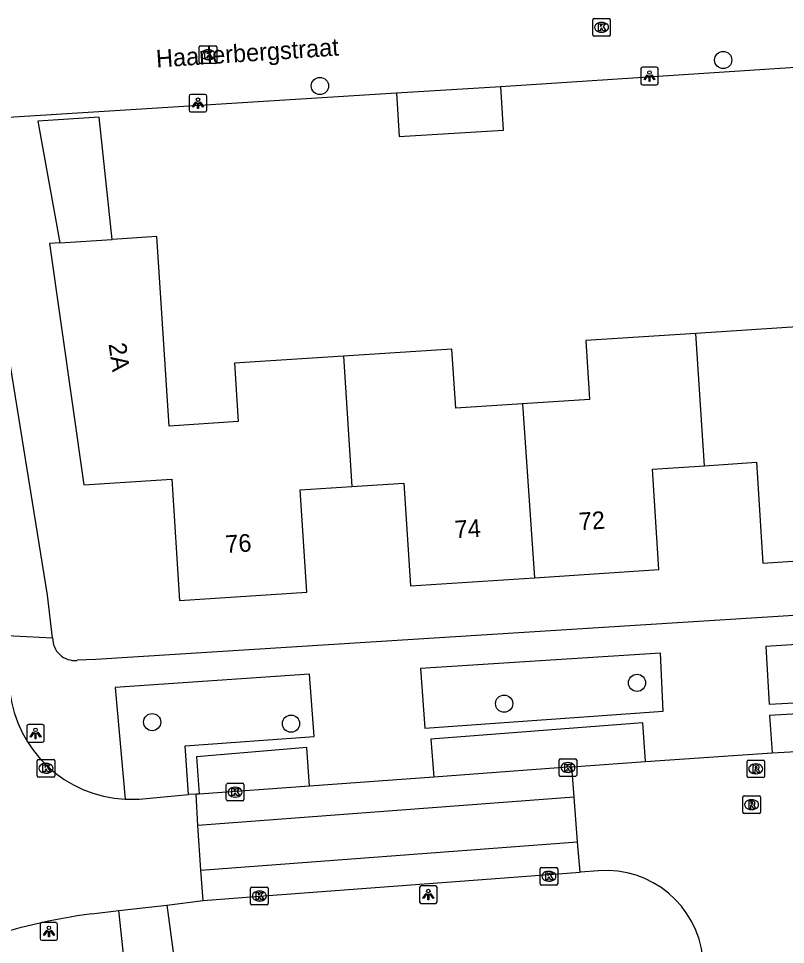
# Model space of a CAD drawing. Extents: x 159689 to 160786, y 387323 to 388339.
# Drawn here: x 160177 to 160220.6, y 388016 to 388068.6 of the extents above; entities that cross this region are included whole.
import ezdxf

# ---------------------------------------------------------------- set-up
doc = ezdxf.new("R2010")
doc.units = 0
for name, color, linetype in [('IMGEO_Boom', 7, 'Continuous'), ('IMGEO_Kolk', 7, 'Continuous'), ('IMGEO_Lichtpunt', 7, 'Continuous'), ('IMGEO_Openbare_ruimte_label', 7, 'Continuous'), ('IMGEO_Pand', 7, 'Continuous'), ('IMGEO_Pand_nummerreeks', 7, 'Continuous'), ('IMGEO_Rijbaan_lokaal_gesloten', 7, 'Continuous'), ('IMGEO_Rijbaan_lokaal_open', 7, 'Continuous'), ('IMGEO_Rioolput', 7, 'Continuous'), ('IMGEO_Voetpad_open', 7, 'Continuous')]:
    doc.layers.add(name, color=color, linetype=linetype)

msp = doc.modelspace()

# ---------------------------------------------------------------- linework, layer by layer
at = {"layer": 'IMGEO_Boom'}
for centre in [(160217.02, 388066.25), (160194.088, 388064.776), (160212.121, 388030.861), (160204.562, 388029.677), (160184.551, 388028.628), (160192.447, 388028.541)]:
    msp.add_circle(centre, 0.489, dxfattribs=at)
at = {"layer": 'IMGEO_Kolk'}
for p, q in [((160209.6, 388067.683), (160209.6, 388068.535)), ((160209.675, 388068.609), (160210.527, 388068.609)), ((160210.088, 388068.389), (160210.113, 388068.389)), ((160210.601, 388068.535), (160210.601, 388067.683)), ((160210.111, 388067.829), (160210.086, 388067.829)), ((160210.527, 388067.609), (160209.675, 388067.609)), ((160187.227, 388066.126), (160187.227, 388066.978)), ((160187.302, 388067.052), (160188.154, 388067.052)), ((160187.715, 388066.832), (160187.74, 388066.832)), ((160188.228, 388066.978), (160188.228, 388066.126)), ((160187.738, 388066.272), (160187.713, 388066.272)), ((160188.154, 388066.052), (160187.302, 388066.052)), ((160178.015, 388025.58), (160178.015, 388026.432)), ((160178.09, 388026.506), (160178.942, 388026.506)), ((160178.503, 388026.286), (160178.528, 388026.286)), ((160179.016, 388026.432), (160179.016, 388025.58)), ((160207.688, 388025.621), (160207.688, 388026.473)), ((160207.763, 388026.547), (160208.615, 388026.547)), ((160208.176, 388026.327), (160208.201, 388026.327)), ((160208.689, 388026.473), (160208.689, 388025.621)), ((160178.526, 388025.726), (160178.501, 388025.726)), ((160208.199, 388025.767), (160208.174, 388025.767)), ((160178.942, 388025.506), (160178.09, 388025.506)), ((160188.767, 388024.225), (160188.767, 388025.077)), ((160188.842, 388025.151), (160189.694, 388025.151)), ((160189.768, 388025.077), (160189.768, 388024.225)), ((160208.615, 388025.547), (160207.763, 388025.547)), ((160189.255, 388024.931), (160189.28, 388024.931)), ((160189.694, 388024.151), (160188.842, 388024.151)), ((160189.278, 388024.371), (160189.253, 388024.371)), ((160206.682, 388020.369), (160207.534, 388020.369)), ((160206.607, 388019.443), (160206.607, 388020.295)), ((160207.095, 388020.149), (160207.12, 388020.149)), ((160207.608, 388020.295), (160207.608, 388019.443)), ((160207.534, 388019.369), (160206.682, 388019.369)), ((160207.118, 388019.589), (160207.093, 388019.589)), ((160190.146, 388018.317), (160190.146, 388019.169)), ((160190.221, 388019.243), (160191.073, 388019.243)), ((160190.634, 388019.023), (160190.659, 388019.023)), ((160191.147, 388019.169), (160191.147, 388018.317)), ((160191.073, 388018.243), (160190.221, 388018.243)), ((160190.657, 388018.463), (160190.632, 388018.463))]:
    msp.add_line(p, q, dxfattribs=at)
for points in [[(160209.6, 388067.683), (160209.6, 388068.535)], [(160209.675, 388068.609), (160210.527, 388068.609)], [(160209.921, 388068.309), (160210.044, 388068.309), (160210.044, 388068.158), (160210.174, 388068.309), (160210.338, 388068.309), (160210.192, 388068.158), (160210.345, 388067.909), (160210.193, 388067.909), (160210.108, 388068.073), (160210.044, 388068.006), (160210.044, 388067.909), (160209.921, 388067.909), (160209.921, 388068.309)], [(160210.601, 388068.535), (160210.601, 388067.683)], [(160210.527, 388067.609), (160209.675, 388067.609)], [(160187.227, 388066.126), (160187.227, 388066.978)], [(160187.302, 388067.052), (160188.154, 388067.052)], [(160187.548, 388066.752), (160187.671, 388066.752), (160187.671, 388066.601), (160187.801, 388066.752), (160187.965, 388066.752), (160187.819, 388066.601), (160187.972, 388066.352), (160187.82, 388066.352), (160187.735, 388066.516), (160187.671, 388066.449), (160187.671, 388066.352), (160187.548, 388066.352), (160187.548, 388066.752)], [(160188.228, 388066.978), (160188.228, 388066.126)], [(160188.154, 388066.052), (160187.302, 388066.052)], [(160178.015, 388025.58), (160178.015, 388026.432)], [(160178.09, 388026.506), (160178.942, 388026.506)], [(160178.336, 388026.206), (160178.459, 388026.206), (160178.459, 388026.055), (160178.589, 388026.206), (160178.753, 388026.206), (160178.607, 388026.055), (160178.76, 388025.806), (160178.608, 388025.806), (160178.523, 388025.97), (160178.459, 388025.903), (160178.459, 388025.806), (160178.336, 388025.806), (160178.336, 388026.206)], [(160179.016, 388026.432), (160179.016, 388025.58)], [(160207.688, 388025.621), (160207.688, 388026.473)], [(160207.763, 388026.547), (160208.615, 388026.547)], [(160208.009, 388026.247), (160208.132, 388026.247), (160208.132, 388026.096), (160208.262, 388026.247), (160208.426, 388026.247), (160208.28, 388026.096), (160208.433, 388025.847), (160208.281, 388025.847), (160208.196, 388026.011), (160208.132, 388025.944), (160208.132, 388025.847), (160208.009, 388025.847), (160208.009, 388026.247)], [(160208.689, 388026.473), (160208.689, 388025.621)], [(160178.942, 388025.506), (160178.09, 388025.506)], [(160188.767, 388024.225), (160188.767, 388025.077)], [(160188.842, 388025.151), (160189.694, 388025.151)], [(160189.768, 388025.077), (160189.768, 388024.225)], [(160208.615, 388025.547), (160207.763, 388025.547)], [(160189.088, 388024.851), (160189.211, 388024.851), (160189.211, 388024.7), (160189.341, 388024.851), (160189.505, 388024.851), (160189.359, 388024.7), (160189.512, 388024.451), (160189.36, 388024.451), (160189.275, 388024.615), (160189.211, 388024.548), (160189.211, 388024.451), (160189.088, 388024.451), (160189.088, 388024.851)], [(160189.694, 388024.151), (160188.842, 388024.151)], [(160206.682, 388020.369), (160207.534, 388020.369)], [(160206.607, 388019.443), (160206.607, 388020.295)], [(160206.928, 388020.069), (160207.051, 388020.069), (160207.051, 388019.918), (160207.181, 388020.069), (160207.345, 388020.069), (160207.199, 388019.918), (160207.352, 388019.669), (160207.2, 388019.669), (160207.115, 388019.833), (160207.051, 388019.766), (160207.051, 388019.669), (160206.928, 388019.669), (160206.928, 388020.069)], [(160207.608, 388020.295), (160207.608, 388019.443)], [(160207.534, 388019.369), (160206.682, 388019.369)], [(160190.146, 388018.317), (160190.146, 388019.169)], [(160190.221, 388019.243), (160191.073, 388019.243)], [(160190.467, 388018.943), (160190.59, 388018.943), (160190.59, 388018.792), (160190.72, 388018.943), (160190.884, 388018.943), (160190.738, 388018.792), (160190.891, 388018.543), (160190.739, 388018.543), (160190.654, 388018.707), (160190.59, 388018.64), (160190.59, 388018.543), (160190.467, 388018.543), (160190.467, 388018.943)], [(160191.147, 388019.169), (160191.147, 388018.317)], [(160191.073, 388018.243), (160190.221, 388018.243)]]:
    msp.add_lwpolyline(points, dxfattribs=at)
for centre, start, end in [((160209.677, 388068.533), 91.552, 178.448), ((160209.677, 388068.533), 91.552, 178.448), ((160210.525, 388068.533), 1.552, 88.448), ((160210.525, 388068.533), 1.552, 88.448), ((160209.677, 388067.685), 181.552, 268.448), ((160209.677, 388067.685), 181.552, 268.448), ((160210.525, 388067.685), 271.552, 358.448), ((160210.525, 388067.685), 271.552, 358.448), ((160187.304, 388066.976), 91.552, 178.448), ((160187.304, 388066.976), 91.552, 178.448), ((160188.152, 388066.976), 1.552, 88.448), ((160188.152, 388066.976), 1.552, 88.448), ((160187.304, 388066.128), 181.552, 268.448), ((160187.304, 388066.128), 181.552, 268.448), ((160188.152, 388066.128), 271.552, 358.448), ((160188.152, 388066.128), 271.552, 358.448), ((160178.092, 388026.43), 91.552, 178.448), ((160178.092, 388026.43), 91.552, 178.448), ((160178.94, 388026.43), 1.552, 88.448), ((160178.94, 388026.43), 1.552, 88.448), ((160207.765, 388026.471), 91.552, 178.448), ((160207.765, 388026.471), 91.552, 178.448), ((160208.613, 388026.471), 1.552, 88.448), ((160208.613, 388026.471), 1.552, 88.448), ((160207.765, 388025.623), 181.552, 268.448), ((160207.765, 388025.623), 181.552, 268.448), ((160208.613, 388025.623), 271.552, 358.448), ((160208.613, 388025.623), 271.552, 358.448), ((160178.092, 388025.582), 181.552, 268.448), ((160178.092, 388025.582), 181.552, 268.448), ((160178.94, 388025.582), 271.552, 358.448), ((160178.94, 388025.582), 271.552, 358.448), ((160188.844, 388025.075), 91.552, 178.448), ((160188.844, 388025.075), 91.552, 178.448), ((160189.692, 388025.075), 1.552, 88.448), ((160189.692, 388025.075), 1.552, 88.448), ((160188.844, 388024.227), 181.552, 268.448), ((160188.844, 388024.227), 181.552, 268.448), ((160189.692, 388024.227), 271.552, 358.448), ((160189.692, 388024.227), 271.552, 358.448), ((160206.684, 388020.293), 91.552, 178.448), ((160206.684, 388020.293), 91.552, 178.448), ((160207.532, 388020.293), 1.552, 88.448), ((160207.532, 388020.293), 1.552, 88.448), ((160206.684, 388019.445), 181.552, 268.448), ((160206.684, 388019.445), 181.552, 268.448), ((160207.532, 388019.445), 271.552, 358.448), ((160207.532, 388019.445), 271.552, 358.448), ((160190.223, 388019.167), 91.552, 178.448), ((160190.223, 388019.167), 91.552, 178.448), ((160191.071, 388019.167), 1.552, 88.448), ((160191.071, 388019.167), 1.552, 88.448), ((160190.223, 388018.319), 181.552, 268.448), ((160190.223, 388018.319), 181.552, 268.448), ((160191.071, 388018.319), 271.552, 358.448), ((160191.071, 388018.319), 271.552, 358.448)]:
    msp.add_arc(centre, 0.0765, start, end, dxfattribs=at)
for centre, major_axis, ratio, start_param, end_param in [((160210.087, 388068.109), (-0.387, 0.002), 0.722429, 4.712389, 7.853982), ((160210.112, 388068.109), (-0.39, 0.002), 0.717154, 1.570796, 4.712389), ((160187.714, 388066.552), (-0.387, 0.002), 0.722429, 4.712389, 7.853982), ((160187.739, 388066.552), (-0.39, 0.002), 0.717154, 1.570796, 4.712389), ((160178.502, 388026.006), (-0.387, 0.002), 0.722429, 4.712389, 7.853982), ((160178.527, 388026.006), (-0.39, 0.002), 0.717154, 1.570796, 4.712389), ((160208.175, 388026.047), (-0.387, 0.002), 0.722429, 4.712389, 7.853982), ((160208.2, 388026.047), (-0.39, 0.002), 0.717154, 1.570796, 4.712389), ((160189.254, 388024.651), (-0.387, 0.002), 0.722429, 4.712389, 7.853982), ((160189.279, 388024.651), (-0.39, 0.002), 0.717154, 1.570796, 4.712389), ((160207.094, 388019.869), (-0.387, 0.002), 0.722429, 4.712389, 7.853982), ((160207.119, 388019.869), (-0.39, 0.002), 0.717154, 1.570796, 4.712389), ((160190.633, 388018.743), (-0.387, 0.002), 0.722429, 4.712389, 7.853982), ((160190.658, 388018.743), (-0.39, 0.002), 0.717154, 1.570796, 4.712389)]:
    msp.add_ellipse(centre, major_axis=major_axis, ratio=ratio, start_param=start_param, end_param=end_param, dxfattribs=at)
at = {"layer": 'IMGEO_Lichtpunt'}
for p, q in [((160212.329, 388065.746), (160212.329, 388064.939)), ((160212.329, 388065.746), (160212.329, 388064.939)), ((160213.231, 388065.841), (160212.423, 388065.841)), ((160213.231, 388065.841), (160212.423, 388065.841)), ((160213.325, 388064.939), (160213.325, 388065.746)), ((160213.325, 388064.939), (160213.325, 388065.746)), ((160212.423, 388064.845), (160213.231, 388064.845)), ((160212.423, 388064.845), (160213.231, 388064.845)), ((160186.655, 388064.204), (160186.655, 388063.397)), ((160186.655, 388064.204), (160186.655, 388063.397)), ((160187.557, 388064.299), (160186.749, 388064.299)), ((160187.557, 388064.299), (160186.749, 388064.299)), ((160187.651, 388063.397), (160187.651, 388064.204)), ((160187.651, 388063.397), (160187.651, 388064.204)), ((160186.749, 388063.303), (160187.557, 388063.303)), ((160186.749, 388063.303), (160187.557, 388063.303)), ((160177.419, 388028.393), (160177.419, 388027.586)), ((160177.419, 388028.393), (160177.419, 388027.586)), ((160178.321, 388028.488), (160177.513, 388028.488)), ((160178.321, 388028.488), (160177.513, 388028.488)), ((160178.415, 388027.586), (160178.415, 388028.393)), ((160178.415, 388027.586), (160178.415, 388028.393)), ((160177.513, 388027.492), (160178.321, 388027.492)), ((160177.513, 388027.492), (160178.321, 388027.492)), ((160200.658, 388019.324), (160199.85, 388019.324)), ((160200.658, 388019.324), (160199.85, 388019.324)), ((160199.756, 388019.229), (160199.756, 388018.422)), ((160199.756, 388019.229), (160199.756, 388018.422)), ((160200.752, 388018.422), (160200.752, 388019.229)), ((160200.752, 388018.422), (160200.752, 388019.229)), ((160199.85, 388018.328), (160200.658, 388018.328)), ((160199.85, 388018.328), (160200.658, 388018.328)), ((160179.082, 388017.232), (160178.274, 388017.232)), ((160179.082, 388017.232), (160178.274, 388017.232)), ((160178.18, 388017.137), (160178.18, 388016.33)), ((160178.18, 388017.137), (160178.18, 388016.33)), ((160179.176, 388016.33), (160179.176, 388017.137)), ((160179.176, 388016.33), (160179.176, 388017.137)), ((160178.274, 388016.236), (160179.082, 388016.236)), ((160178.274, 388016.236), (160179.082, 388016.236))]:
    msp.add_line(p, q, dxfattribs=at)
for points in [[(160212.703, 388065.41), (160212.742, 388065.382), (160212.554, 388065.12), (160212.516, 388065.147), (160212.703, 388065.41)], [(160212.805, 388065.362), (160212.852, 388065.362), (160212.852, 388065.04), (160212.805, 388065.04), (160212.805, 388065.362)], [(160212.915, 388065.382), (160212.953, 388065.409), (160213.14, 388065.147), (160213.101, 388065.119), (160212.915, 388065.382)], [(160187.029, 388063.868), (160187.068, 388063.84), (160186.88, 388063.578), (160186.842, 388063.605), (160187.029, 388063.868)], [(160187.131, 388063.82), (160187.178, 388063.82), (160187.178, 388063.498), (160187.131, 388063.498), (160187.131, 388063.82)], [(160187.241, 388063.84), (160187.279, 388063.867), (160187.466, 388063.605), (160187.427, 388063.577), (160187.241, 388063.84)], [(160177.793, 388028.057), (160177.832, 388028.029), (160177.644, 388027.767), (160177.606, 388027.794), (160177.793, 388028.057)], [(160177.895, 388028.009), (160177.942, 388028.009), (160177.942, 388027.687), (160177.895, 388027.687), (160177.895, 388028.009)], [(160178.005, 388028.029), (160178.043, 388028.056), (160178.23, 388027.794), (160178.191, 388027.766), (160178.005, 388028.029)], [(160200.13, 388018.893), (160200.169, 388018.865), (160199.981, 388018.603), (160199.943, 388018.63), (160200.13, 388018.893)], [(160200.232, 388018.845), (160200.279, 388018.845), (160200.279, 388018.523), (160200.232, 388018.523), (160200.232, 388018.845)], [(160200.342, 388018.865), (160200.38, 388018.892), (160200.567, 388018.63), (160200.528, 388018.602), (160200.342, 388018.865)], [(160178.554, 388016.801), (160178.593, 388016.773), (160178.405, 388016.511), (160178.367, 388016.538), (160178.554, 388016.801)], [(160178.656, 388016.753), (160178.703, 388016.753), (160178.703, 388016.431), (160178.656, 388016.431), (160178.656, 388016.753)], [(160178.766, 388016.773), (160178.804, 388016.8), (160178.991, 388016.538), (160178.952, 388016.51), (160178.766, 388016.773)]]:
    msp.add_lwpolyline(points, dxfattribs=at)
for centre in [(160212.828, 388065.544), (160187.154, 388064.002), (160177.918, 388028.191), (160200.255, 388019.027), (160178.679, 388016.935)]:
    msp.add_circle(centre, 0.0994, dxfattribs=at)
for centre, start, end in [((160212.423, 388065.746), 90, 180), ((160212.423, 388065.746), 90, 180), ((160213.231, 388065.746), 0, 90), ((160213.231, 388065.746), 0, 90), ((160212.423, 388064.939), 180, 270), ((160212.423, 388064.939), 180, 270), ((160213.231, 388064.939), 270, 0), ((160213.231, 388064.939), 270, 360), ((160186.749, 388064.204), 90, 180), ((160186.749, 388064.204), 90, 180), ((160187.557, 388064.204), 0, 90), ((160187.557, 388064.204), 0, 90), ((160186.749, 388063.397), 180, 270), ((160186.749, 388063.397), 180, 270), ((160187.557, 388063.397), 270, 0), ((160187.557, 388063.397), 270, 360), ((160177.513, 388028.393), 90, 180), ((160177.513, 388028.393), 90, 180), ((160178.321, 388028.393), 0, 90), ((160178.321, 388028.393), 0, 90), ((160177.513, 388027.586), 180, 270), ((160177.513, 388027.586), 180, 270), ((160178.321, 388027.586), 270, 0), ((160178.321, 388027.586), 270, 360), ((160199.85, 388019.229), 90, 180), ((160199.85, 388019.229), 90, 180), ((160200.658, 388019.229), 0, 90), ((160200.658, 388019.229), 0, 90), ((160199.85, 388018.422), 180, 270), ((160199.85, 388018.422), 180, 270), ((160200.658, 388018.422), 270, 0), ((160200.658, 388018.422), 270, 360), ((160178.274, 388017.137), 90, 180), ((160178.274, 388017.137), 90, 180), ((160179.082, 388017.137), 0, 90), ((160179.082, 388017.137), 0, 90), ((160178.274, 388016.33), 180, 270), ((160178.274, 388016.33), 180, 270), ((160179.082, 388016.33), 270, 0), ((160179.082, 388016.33), 270, 360)]:
    msp.add_arc(centre, 0.0946, start, end, dxfattribs=at)
at = {"layer": 'IMGEO_Pand'}
for points in [[(160198.437, 388064.384), (160204.372, 388064.747)], [(160198.437, 388064.384), (160198.588, 388061.908), (160204.523, 388062.271), (160204.372, 388064.747)], [(160182.285, 388056.056), (160181.54, 388063.003), (160178.058, 388062.786), (160179.293, 388055.862)], [(160195.425, 388049.427), (160189.224, 388049.025), (160189.439, 388045.706), (160185.518, 388045.452), (160184.82, 388056.22), (160182.285, 388056.056)], [(160179.293, 388055.862), (160178.714, 388055.824), (160180.656, 388042.111), (160185.665, 388042.435), (160186.112, 388035.539), (160193.342, 388036.008), (160192.965, 388041.822), (160195.91, 388042.013)], [(160179.293, 388055.862), (160182.285, 388056.056)], [(160215.952, 388043.198), (160218.91, 388043.39), (160219.281, 388037.669), (160226.355, 388038.127), (160225.716, 388047.979), (160221.727, 388047.72), (160221.507, 388051.109), (160215.463, 388050.717)], [(160215.463, 388050.717), (160209.207, 388050.312), (160209.424, 388046.955), (160205.609, 388046.708)], [(160215.952, 388043.198), (160215.463, 388050.717)], [(160205.609, 388046.708), (160201.807, 388046.461), (160201.589, 388049.826), (160195.425, 388049.427)], [(160195.425, 388049.427), (160195.91, 388042.013)], [(160205.609, 388046.708), (160206.287, 388036.836)], [(160206.287, 388036.836), (160213.366, 388037.295), (160212.995, 388043.007), (160215.952, 388043.198)], [(160195.91, 388042.013), (160198.855, 388042.204), (160199.232, 388036.379), (160206.287, 388036.836)]]:
    msp.add_lwpolyline(points, dxfattribs=at)
at = {"layer": 'IMGEO_Rijbaan_lokaal_gesloten'}
for points in [[(160208.416, 388026.088), (160200.562, 388025.508)], [(160208.542, 388024.371), (160208.416, 388026.088)], [(160200.562, 388025.508), (160193.492, 388024.989)], [(160187.154, 388022.762), (160187.053, 388024.539)], [(160187.216, 388024.532), (160187.053, 388024.539)], [(160193.492, 388024.989), (160187.216, 388024.532)], [(160208.542, 388024.371), (160187.154, 388022.762)], [(160187.317, 388020.219), (160208.743, 388021.816)], [(160208.888, 388020.103), (160208.743, 388021.816)], [(160187.441, 388018.496), (160187.317, 388020.219)], [(160187.441, 388018.496), (160190.647, 388018.743), (160208.888, 388020.103)]]:
    msp.add_lwpolyline(points, dxfattribs=at)
at = {"layer": 'IMGEO_Rijbaan_lokaal_open'}
for points in [[(160219.812, 388026.875), (160225.582, 388027.211)], [(160212.61, 388026.399), (160219.812, 388026.875)], [(160208.416, 388026.088), (160212.61, 388026.399)], [(160187.053, 388024.539), (160186.613, 388024.507)], [(160183.022, 388024.242), (160183.807, 388024.248), (160186.613, 388024.507)], [(160208.743, 388021.816), (160208.542, 388024.371)], [(160187.317, 388020.219), (160187.154, 388022.762)], [(160209.919, 388020.182), (160208.888, 388020.103)], [(160182.649, 388017.928), (160185.385, 388018.228)], [(160185.385, 388018.228), (160187.441, 388018.496)], [(160181.114, 388017.734), (160182.649, 388017.928)]]:
    msp.add_lwpolyline(points, dxfattribs=at)
for centre, radius, start, end in [((160183.372, 388031.213), 6.979, 186.7029, 267.128), ((160210.346, 388014.647), 5.552, 5.7931, 94.4161), ((160185.806, 387982.905), 35.144, 97.6718, 119.3652)]:
    msp.add_arc(centre, radius, start, end, dxfattribs=at)
at = {"layer": 'IMGEO_Rioolput'}
for p, q in [((160218.372, 388025.547), (160218.372, 388026.399)), ((160218.447, 388026.473), (160219.299, 388026.473)), ((160218.86, 388026.253), (160218.885, 388026.253)), ((160219.373, 388026.399), (160219.373, 388025.547)), ((160218.883, 388025.693), (160218.858, 388025.693)), ((160219.299, 388025.473), (160218.447, 388025.473)), ((160218.132, 388023.511), (160218.132, 388024.363)), ((160218.207, 388024.437), (160219.059, 388024.437)), ((160218.62, 388024.217), (160218.645, 388024.217)), ((160219.133, 388024.363), (160219.133, 388023.511)), ((160218.643, 388023.657), (160218.618, 388023.657)), ((160219.059, 388023.437), (160218.207, 388023.437))]:
    msp.add_line(p, q, dxfattribs=at)
for points in [[(160218.372, 388025.547), (160218.372, 388026.399)], [(160218.447, 388026.473), (160219.299, 388026.473)], [(160218.961, 388026.171), (160218.709, 388026.173), (160218.709, 388025.773)], [(160219.373, 388026.399), (160219.373, 388025.547)], [(160218.709, 388025.773), (160218.833, 388025.773), (160218.833, 388025.935), (160218.844, 388025.935)], [(160218.887, 388026.092), (160218.833, 388026.092), (160218.833, 388026.011)], [(160218.833, 388026.011), (160218.885, 388026.011)], [(160218.891, 388025.906), (160218.962, 388025.773), (160219.102, 388025.773), (160219.037, 388025.899)], [(160219.299, 388025.473), (160218.447, 388025.473)], [(160218.132, 388023.511), (160218.132, 388024.363)], [(160218.207, 388024.437), (160219.059, 388024.437)], [(160218.721, 388024.135), (160218.469, 388024.137), (160218.469, 388023.737)], [(160218.647, 388024.056), (160218.593, 388024.056), (160218.593, 388023.975)], [(160219.133, 388024.363), (160219.133, 388023.511)], [(160218.469, 388023.737), (160218.593, 388023.737), (160218.593, 388023.899), (160218.604, 388023.899)], [(160218.593, 388023.975), (160218.645, 388023.975)], [(160218.651, 388023.87), (160218.722, 388023.737), (160218.862, 388023.737), (160218.797, 388023.863)], [(160219.059, 388023.437), (160218.207, 388023.437)]]:
    msp.add_lwpolyline(points, dxfattribs=at)
for centre, radius, start, end in [((160218.449, 388026.397), 0.0765, 91.552, 178.448), ((160218.449, 388026.397), 0.0765, 91.552, 178.448), ((160218.96, 388026.061), 0.109, 350.3612, 89.416), ((160219.297, 388026.397), 0.0765, 1.552, 88.448), ((160219.297, 388026.397), 0.0765, 1.552, 88.448), ((160218.843, 388025.882), 0.0533, 26.0293, 88.6989), ((160218.869, 388026.2), 0.19, 274.7715, 282.9687), ((160218.893, 388025.996), 0.0964, 77.0061, 93.1865), ((160218.907, 388026.053), 0.0378, 276.6634, 79.6772), ((160218.958, 388026.061), 0.112, 277.5842, 350.9817), ((160218.942, 388025.846), 0.108, 29.5134, 73.7905), ((160218.449, 388025.549), 0.0765, 181.552, 268.448), ((160218.449, 388025.549), 0.0765, 181.552, 268.448), ((160219.297, 388025.549), 0.0765, 271.552, 358.448), ((160219.297, 388025.549), 0.0765, 271.552, 358.448), ((160218.209, 388024.361), 0.0765, 91.552, 178.448), ((160218.209, 388024.361), 0.0765, 91.552, 178.448), ((160218.653, 388023.96), 0.0964, 77.0061, 93.1865), ((160218.667, 388024.017), 0.0378, 276.6634, 79.6772), ((160218.72, 388024.025), 0.109, 350.3612, 89.416), ((160219.057, 388024.361), 0.0765, 1.552, 88.448), ((160219.057, 388024.361), 0.0765, 1.552, 88.448), ((160218.209, 388023.513), 0.0765, 181.552, 268.448), ((160218.209, 388023.513), 0.0765, 181.552, 268.448), ((160218.603, 388023.846), 0.0533, 26.0293, 88.6989), ((160218.629, 388024.164), 0.19, 274.7715, 282.9687), ((160218.718, 388024.025), 0.112, 277.5842, 350.9817), ((160218.702, 388023.81), 0.108, 29.5134, 73.7905), ((160219.057, 388023.513), 0.0765, 271.552, 358.448), ((160219.057, 388023.513), 0.0765, 271.552, 358.448)]:
    msp.add_arc(centre, radius, start, end, dxfattribs=at)
for centre, major_axis, ratio, start_param, end_param in [((160218.859, 388025.973), (-0.387, 0.002), 0.722429, 4.712389, 7.853982), ((160218.884, 388025.973), (-0.39, 0.002), 0.717154, 1.570796, 4.712389), ((160218.619, 388023.937), (-0.387, 0.002), 0.722429, 4.712389, 7.853982), ((160218.644, 388023.937), (-0.39, 0.002), 0.717154, 1.570796, 4.712389)]:
    msp.add_ellipse(centre, major_axis=major_axis, ratio=ratio, start_param=start_param, end_param=end_param, dxfattribs=at)
at = {"layer": 'IMGEO_Voetpad_open'}
for points in [[(160204.372, 388064.747), (160224.579, 388066.073)], [(160176.383, 388063.009), (160198.437, 388064.384)], [(160178.891, 388033.423), (160178.592, 388035.844), (160174.553, 388060.734)], [(160227.952, 388035.127), (160181.347, 388032.191), (160180.287, 388032.139)], [(160175.918, 388033.57), (160178.891, 388033.423)], [(160229.479, 388028.101), (160229.125, 388033.548), (160219.446, 388032.924), (160219.639, 388029.651), (160226.031, 388029.99), (160226.174, 388027.215)], [(160199.813, 388031.684), (160200.047, 388028.289), (160213.607, 388029.258), (160213.446, 388032.538), (160199.813, 388031.684)], [(160186.613, 388024.507), (160186.433, 388027.277), (160193.763, 388027.81), (160193.493, 388031.345), (160182.445, 388030.599), (160183.022, 388024.242)], [(160225.582, 388027.211), (160225.463, 388029.353), (160219.659, 388029.012), (160219.812, 388026.875)], [(160212.61, 388026.399), (160212.448, 388028.584), (160200.391, 388027.665), (160200.562, 388025.508)], [(160193.492, 388024.989), (160193.342, 388027.188), (160187.071, 388026.659), (160187.216, 388024.532)], [(160185.385, 388018.228), (160185.81, 388015.147), (160186.254, 388011.402)], [(160183.072, 388014.047), (160182.649, 388017.928)]]:
    msp.add_lwpolyline(points, dxfattribs=at)
msp.add_arc((160180.151, 388033.392), 1.261, 178.605, 276.1811, dxfattribs=at)

# ---------------------------------------------------------------- texts
at = {"layer": 'IMGEO_Openbare_ruimte_label'}
msp.add_text('Haarlerbergstraat', height=1, rotation=3.7836, dxfattribs=at).set_placement((160184.801, 388065.82))
at = {"layer": 'IMGEO_Pand_nummerreeks'}
for s, rotation, p in [('2A', 278.0613, (160182.067, 388050.118)), ('72', 3.7081, (160208.842, 388039.527)), ('74', 3.7081, (160201.778, 388039.07)), ('76', 3.7128, (160188.739, 388038.235))]:
    msp.add_text(s, height=1, rotation=rotation, dxfattribs=at).set_placement(p)

doc.saveas('drawing.dxf')
